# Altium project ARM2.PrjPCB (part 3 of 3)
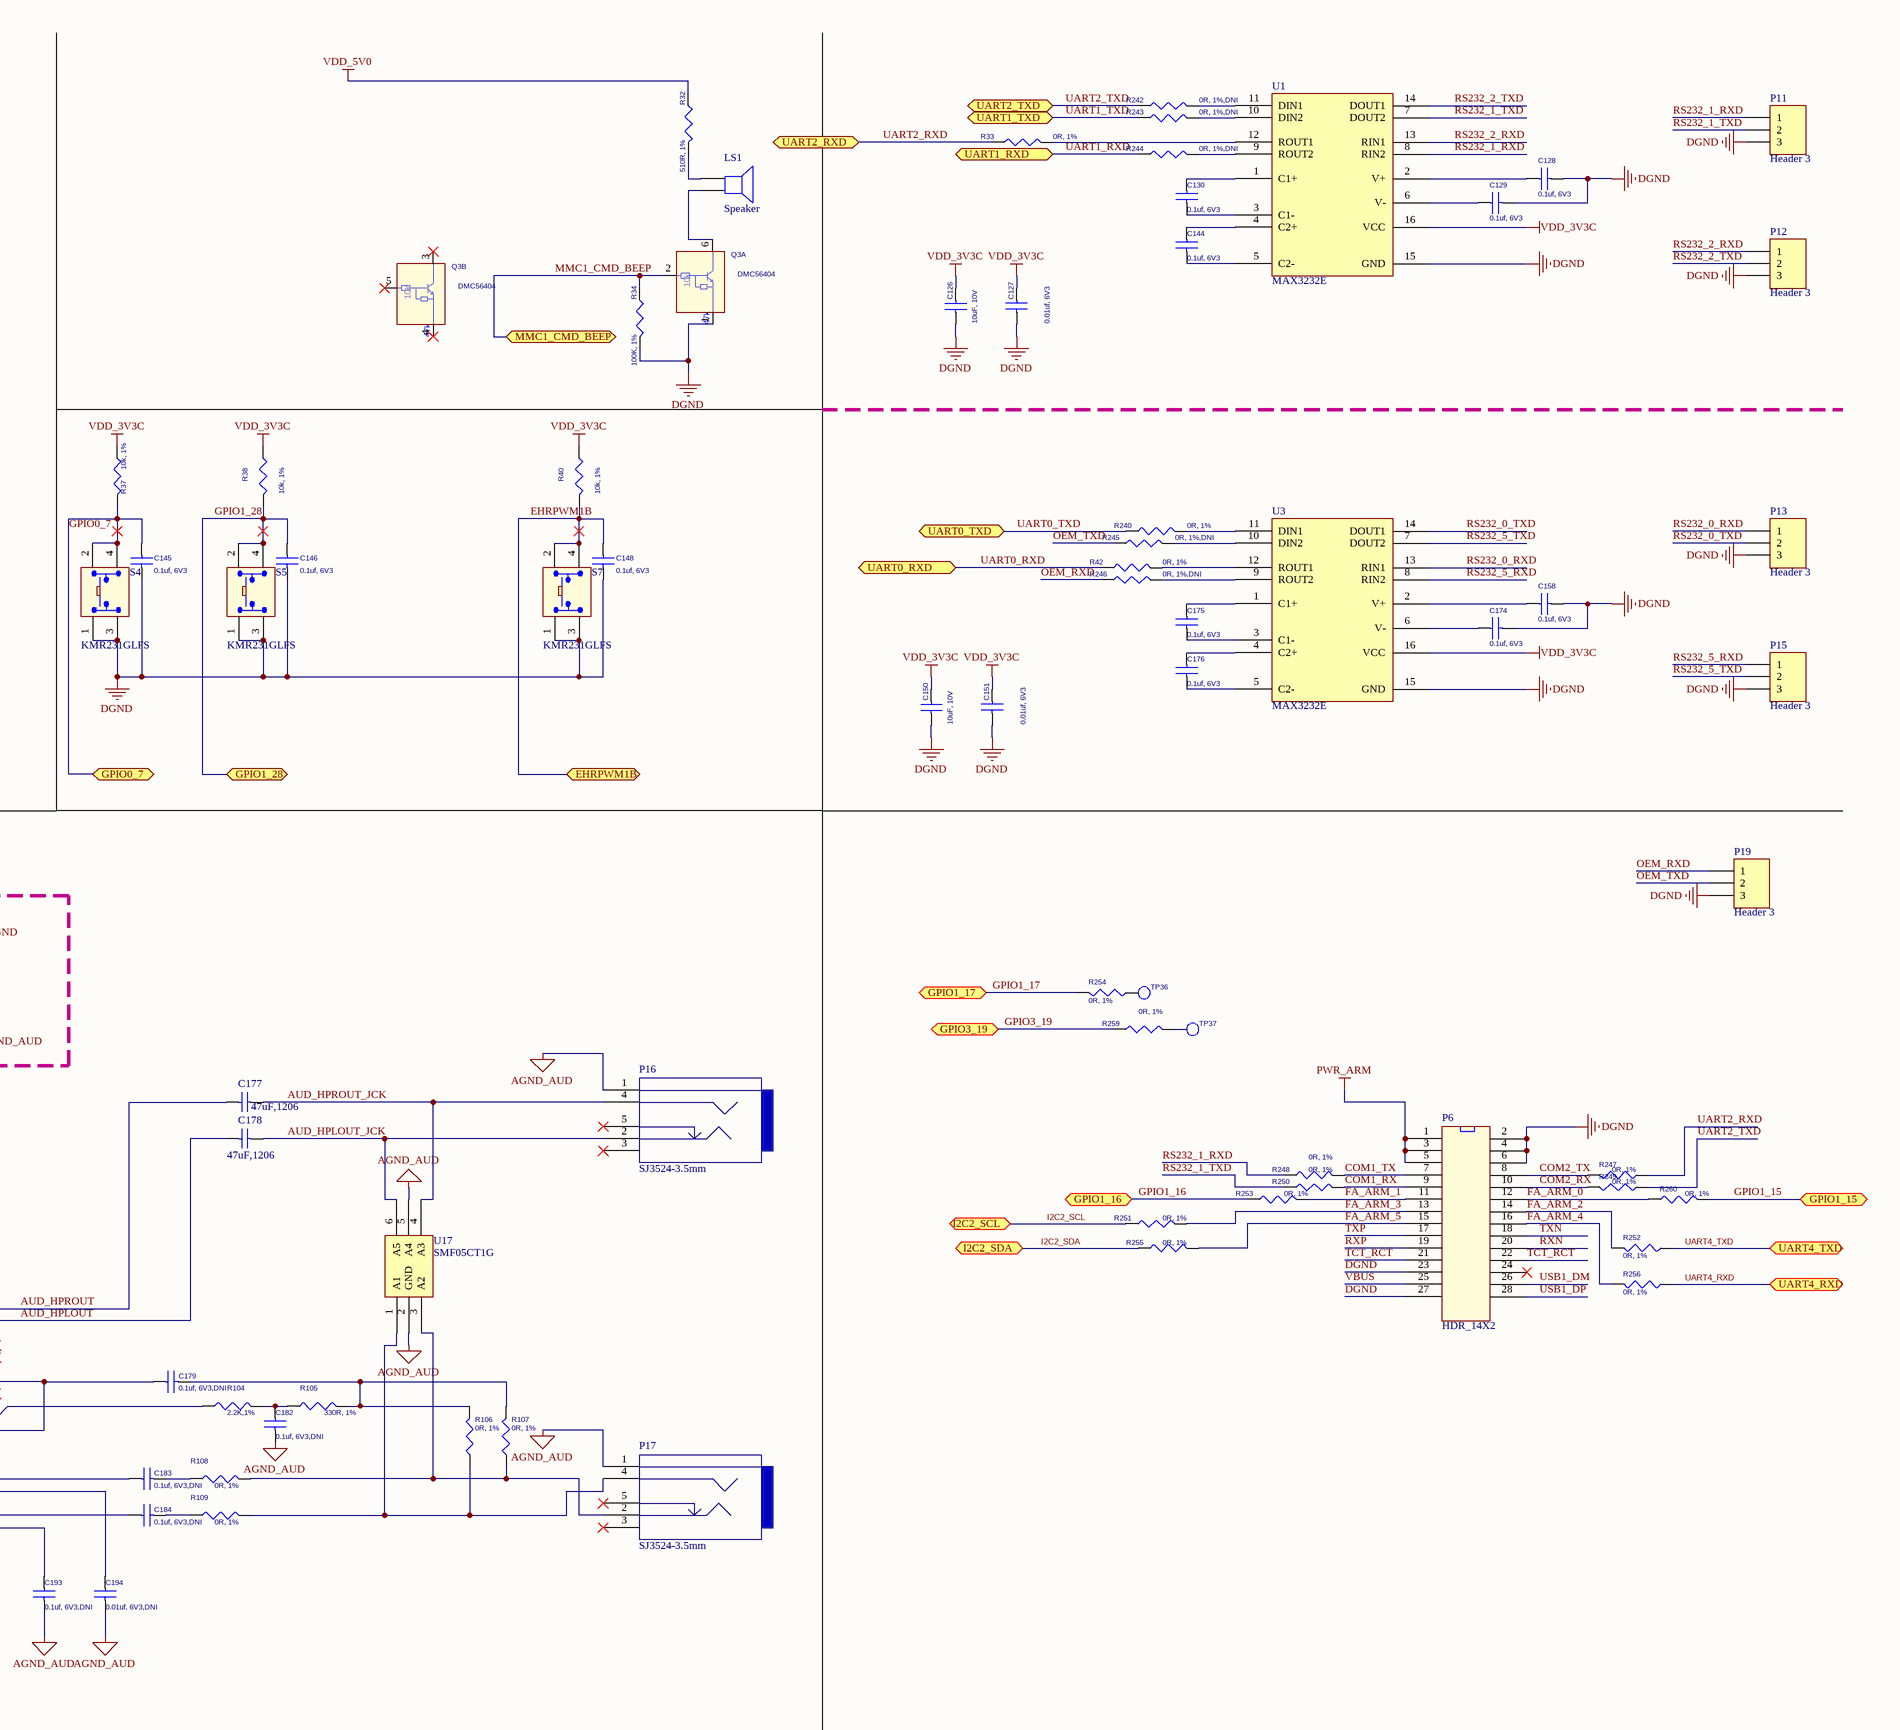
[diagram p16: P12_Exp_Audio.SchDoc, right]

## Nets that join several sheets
DDR_VREF: P03_Processor1_3 (C28.1 U5.J4), P07_DDR3_SDRAM (6 pins)
DGND: P02_PowerManagement (33 pins), P03_Processor1_3 (14 pins), P04_Processor2_3 (16 pins), P05_Processor3_3 (111 pins), P06_LED_BootConfig (26 pins), P07_DDR3_SDRAM (42 pins), P08_NandFlash (5 pins), P09_Ethernet (23 pins), P10_LCD (142 pins), P11_SDcard (7 pins), P12_Exp_Audio (46 pins)
GND_EARTH: P02_PowerManagement (6 pins), P04_Processor2_3 (P4.6 P4.7 P4.8 P4.9), P11_SDcard (6 pins)
GNDA_ADC: P04_Processor2_3 (C31.2 C32.2 C33.2 U5.A9), P05_Processor3_3 (C93.2 FB3.1 U5.E8), P11_SDcard (TP31.1)
SYS_5V: P02_PowerManagement (14 pins), P04_Processor2_3 (C34.1 U8.2 U8.3), P06_LED_BootConfig (R71.1 R72.1 R73.1 R74.1), P10_LCD (C200.1 U20.2), P11_SDcard (TP12.1)
USB_DC: P02_PowerManagement (C1.2 U2.12), P04_Processor2_3 (C36.1 P4.1 R159.1 U10.6)
VDD_1V8: P02_PowerManagement (C14.2 R9.2 U2.40), P05_Processor3_3 (9 pins)
VDD_3V3A: P02_PowerManagement (6 pins), P03_Processor1_3 (7 pins), P04_Processor2_3 (R52.1), P05_Processor3_3 (42 pins), P06_LED_BootConfig (16 pins), P10_LCD (U20.1), P11_SDcard (C152.1 R156.1 U7.4)
VDD_3V3B: P02_PowerManagement (C20.1 R11.1 U4.3), P03_Processor1_3 (C29.1 R23.1 R24.1), P04_Processor2_3 (C155.2 R163.1 U15.7 U15.8), P08_NandFlash (12 pins), P09_Ethernet (7 pins), P10_LCD (R158.1), P11_SDcard (11 pins)
VDD_5V: P02_PowerManagement (C2.2 R239.2 U2.10), P11_SDcard (TP11.1), P12_Exp_Audio (FB5.2)
VDD_5V0: P10_LCD (FB17.1 P9.1), P12_Exp_Audio (8 pins)
VDD_ADC: P04_Processor2_3 (R27.1), P05_Processor3_3 (C93.1 FB2.1 U5.D8), P11_SDcard (TP29.1)
VDD_CORE: P02_PowerManagement (C11.2 L3.2 U2.29), P05_Processor3_3 (37 pins)
VDD_MPU: P02_PowerManagement (C12.2 L2.2 U2.24), P05_Processor3_3 (11 pins)
VDDS: P02_PowerManagement (R8.2 R9.1), P05_Processor3_3 (13 pins)
VDDS_DDR: P02_PowerManagement (C9.2 R6.2), P05_Processor3_3 (16 pins), P07_DDR3_SDRAM (36 pins)
VIO: P02_PowerManagement (R7.2 U2.18), P03_Processor1_3 (U16.5)
VRTC: P02_PowerManagement (C16.1 R5.2), P04_Processor2_3 (R26.1), P05_Processor3_3 (C105.1 U5.D7)
12MHZ: P03_Processor1_3 (R21.2), P12_Exp_Audio (R103.1)
AIN4: P04_Processor2_3 (U5.C8), P11_SDcard (TP30.1)
AIN5: P04_Processor2_3 (U5.B8), P11_SDcard (TP33.1)
AIN6: P04_Processor2_3 (U5.A8), P11_SDcard (TP32.1)
CLKOUT2: P03_Processor1_3 (R19.2 R20.1), P11_SDcard (TP34.1)
DDR_A0: P03_Processor1_3 (U5.F3), P07_DDR3_SDRAM (U12.N3)
DDR_A1: P03_Processor1_3 (U5.H1), P07_DDR3_SDRAM (U12.P7)
DDR_A2: P03_Processor1_3 (U5.E4), P07_DDR3_SDRAM (U12.P3)
DDR_A3: P03_Processor1_3 (U5.C3), P07_DDR3_SDRAM (U12.N2)
DDR_A4: P03_Processor1_3 (U5.C2), P07_DDR3_SDRAM (U12.P8)
DDR_A5: P03_Processor1_3 (U5.B1), P07_DDR3_SDRAM (U12.P2)
DDR_A6: P03_Processor1_3 (U5.D5), P07_DDR3_SDRAM (U12.R8)
DDR_A7: P03_Processor1_3 (U5.E2), P07_DDR3_SDRAM (U12.R2)
DDR_A8: P03_Processor1_3 (U5.D4), P07_DDR3_SDRAM (U12.T8)
DDR_A9: P03_Processor1_3 (U5.C1), P07_DDR3_SDRAM (U12.R3)
DDR_A10: P03_Processor1_3 (U5.F4), P07_DDR3_SDRAM (U12.L7)
DDR_A11: P03_Processor1_3 (U5.F2), P07_DDR3_SDRAM (U12.R7)
DDR_A12: P03_Processor1_3 (U5.E3), P07_DDR3_SDRAM (U12.N7)
DDR_A13: P03_Processor1_3 (U5.H3), P07_DDR3_SDRAM (U12.T3)
DDR_A14: P03_Processor1_3 (U5.H4), P07_DDR3_SDRAM (U12.T7)
DDR_A15: P03_Processor1_3 (U5.D3), P07_DDR3_SDRAM (U12.M7)
DDR_BA0: P03_Processor1_3 (U5.C4), P07_DDR3_SDRAM (U12.M2)
DDR_BA1: P03_Processor1_3 (U5.E1), P07_DDR3_SDRAM (U12.N8)
DDR_BA2: P03_Processor1_3 (U5.B3), P07_DDR3_SDRAM (U12.M3)
DDR_CASn: P03_Processor1_3 (U5.F1), P07_DDR3_SDRAM (U12.K3)
DDR_CKE: P03_Processor1_3 (U5.G3), P07_DDR3_SDRAM (R96.2 U12.K9)
DDR_CLK: P03_Processor1_3 (U5.D2), P07_DDR3_SDRAM (U12.J7)
DDR_CLKn: P03_Processor1_3 (U5.D1), P07_DDR3_SDRAM (U12.K7)
DDR_CSn: P03_Processor1_3 (U5.H2), P07_DDR3_SDRAM (U12.L2)
DDR_D0: P03_Processor1_3 (U5.M3), P07_DDR3_SDRAM (U12.E3)
DDR_D1: P03_Processor1_3 (U5.M4), P07_DDR3_SDRAM (U12.F7)
DDR_D2: P03_Processor1_3 (U5.N1), P07_DDR3_SDRAM (U12.F2)
DDR_D3: P03_Processor1_3 (U5.N2), P07_DDR3_SDRAM (U12.F8)
DDR_D4: P03_Processor1_3 (U5.N3), P07_DDR3_SDRAM (U12.H3)
DDR_D5: P03_Processor1_3 (U5.N4), P07_DDR3_SDRAM (U12.H8)
DDR_D6: P03_Processor1_3 (U5.P3), P07_DDR3_SDRAM (U12.G2)
DDR_D7: P03_Processor1_3 (U5.P4), P07_DDR3_SDRAM (U12.H7)
DDR_D8: P03_Processor1_3 (U5.J1), P07_DDR3_SDRAM (U12.D7)
DDR_D9: P03_Processor1_3 (U5.K1), P07_DDR3_SDRAM (U12.C3)
DDR_D10: P03_Processor1_3 (U5.K2), P07_DDR3_SDRAM (U12.C8)
DDR_D11: P03_Processor1_3 (U5.K3), P07_DDR3_SDRAM (U12.C2)
DDR_D12: P03_Processor1_3 (U5.K4), P07_DDR3_SDRAM (U12.A7)
DDR_D13: P03_Processor1_3 (U5.L3), P07_DDR3_SDRAM (U12.A2)
DDR_D14: P03_Processor1_3 (U5.L4), P07_DDR3_SDRAM (U12.B8)
DDR_D15: P03_Processor1_3 (U5.M1), P07_DDR3_SDRAM (U12.A3)
DDR_DQM0: P03_Processor1_3 (U5.M2), P07_DDR3_SDRAM (U12.E7)
DDR_DQM1: P03_Processor1_3 (U5.J2), P07_DDR3_SDRAM (U12.D3)
DDR_DQS0: P03_Processor1_3 (U5.P1), P07_DDR3_SDRAM (U12.F3)
DDR_DQS1: P03_Processor1_3 (U5.L1), P07_DDR3_SDRAM (U12.C7)
DDR_DQSN0: P03_Processor1_3 (U5.P2), P07_DDR3_SDRAM (U12.G3)
DDR_DQSN1: P03_Processor1_3 (U5.L2), P07_DDR3_SDRAM (U12.B7)
DDR_ODT: P03_Processor1_3 (U5.G1), P07_DDR3_SDRAM (U12.K1)
DDR_RASn: P03_Processor1_3 (U5.G4), P07_DDR3_SDRAM (U12.J3)
DDR_RESETn: P03_Processor1_3 (U5.G2), P07_DDR3_SDRAM (R97.2 U12.T2)
DDR_WEn: P03_Processor1_3 (U5.B2), P07_DDR3_SDRAM (U12.L3)
EHRPWM1A: P03_Processor1_3 (U5.U14), P11_SDcard (TP18.1)
EHRPWM1B: P03_Processor1_3 (U5.T14), P11_SDcard (TP19.1), P12_Exp_Audio (C148.1 R40.2 S7.2 S7.4)
GPIO0_7: P04_Processor2_3 (R50.1 R51.1), P11_SDcard (TP35.1), P12_Exp_Audio (C145.1 R37.2 S4.2 S4.4)
GPIO1_15: P03_Processor1_3 (U5.U13), P12_Exp_Audio (R260.2)
GPIO1_16: P03_Processor1_3 (R160.2), P12_Exp_Audio (R253.1)
GPIO1_17: P03_Processor1_3 (U5.V14), P12_Exp_Audio (R254.2)
GPIO1_28: P03_Processor1_3 (U5.U18), P11_SDcard (TP16.1), P12_Exp_Audio (C146.1 R38.2 S5.2 S5.4)
GPIO3_19: P04_Processor2_3 (U5.C13), P12_Exp_Audio (R259.1)
GPIO3_20: P03_Processor1_3 (R20.2), P04_Processor2_3 (U5.D13)
GPIO3_21: P03_Processor1_3 (R167.2), P04_Processor2_3 (U5.A14), P11_SDcard (TP24.1), P12_Exp_Audio (R102.1)
HDMI_INT: P03_Processor1_3 (U5.U16), P10_LCD (R158.2)
I2C0_SCL: P02_PowerManagement (R3.2 U2.28), P04_Processor2_3 (U5.C16), P11_SDcard (U7.1)
I2C0_SDA: P02_PowerManagement (R4.2 U2.27), P04_Processor2_3 (U5.C17), P11_SDcard (U7.3)
I2C1_SCL: P04_Processor2_3 (U5.A16), P11_SDcard (TP20.1), P12_Exp_Audio (U11.1)
I2C1_SDA: P04_Processor2_3 (U5.B16), P11_SDcard (TP21.1), P12_Exp_Audio (U11.2)
I2C2_SCL: P04_Processor2_3 (U5.D17), P11_SDcard (TP22.1), P12_Exp_Audio (R251.1)
I2C2_SDA: P04_Processor2_3 (U5.D18), P11_SDcard (TP23.1), P12_Exp_Audio (R255.1)
LCD_DATA0: P04_Processor2_3 (U5.R1), P06_LED_BootConfig (R70.2 R95.1), P10_LCD (C173.1 RA5.2)
LCD_DATA1: P04_Processor2_3 (U5.R2), P06_LED_BootConfig (R69.2 R94.1), P10_LCD (C171.1 RA5.3)
LCD_DATA2: P04_Processor2_3 (U5.R3), P06_LED_BootConfig (R68.2 R75.1 R93.1), P10_LCD (C172.1 RA5.4)
LCD_DATA3: P04_Processor2_3 (U5.R4), P06_LED_BootConfig (R67.2 R92.1), P10_LCD (C170.1 RA6.1)
LCD_DATA4: P04_Processor2_3 (U5.T1), P06_LED_BootConfig (R66.2 R91.1), P10_LCD (C169.1 RA6.2)
LCD_DATA5: P04_Processor2_3 (U5.T2), P06_LED_BootConfig (R65.2 R90.1), P10_LCD (C163.1 RA3.3)
LCD_DATA6: P04_Processor2_3 (U5.T3), P06_LED_BootConfig (R64.2 R89.1), P10_LCD (C162.1 RA3.4)
LCD_DATA7: P04_Processor2_3 (U5.T4), P06_LED_BootConfig (R63.2 R88.1), P10_LCD (C161.1 RA4.1)
LCD_DATA8: P04_Processor2_3 (U5.U1), P06_LED_BootConfig (R62.2 R87.1), P10_LCD (C160.1 RA4.2)
LCD_DATA9: P04_Processor2_3 (U5.U2), P06_LED_BootConfig (R61.2 R86.1), P10_LCD (C157.1 RA4.3)
LCD_DATA10: P04_Processor2_3 (U5.U3), P06_LED_BootConfig (R60.2 R85.1), P10_LCD (C156.1 RA4.4)
LCD_DATA11: P04_Processor2_3 (U5.U4), P06_LED_BootConfig (R59.2 R84.1), P10_LCD (C168.1 RA2.2)
LCD_DATA12: P04_Processor2_3 (U5.V2), P06_LED_BootConfig (R58.2 R83.1), P10_LCD (C167.1 RA2.3)
LCD_DATA13: P04_Processor2_3 (U5.V3), P06_LED_BootConfig (R57.2 R82.1), P10_LCD (C166.1 RA2.4)
LCD_DATA14: P04_Processor2_3 (U5.V4), P06_LED_BootConfig (R56.2 R81.1), P10_LCD (C165.1 RA3.1)
LCD_DATA15: P04_Processor2_3 (U5.T5), P06_LED_BootConfig (R55.2 R80.1), P10_LCD (C164.1 RA3.2)
LCD_DE: P04_Processor2_3 (R48.2), P10_LCD (RA6.3)
LCD_HSYNC: P04_Processor2_3 (R47.2), P10_LCD (RA1.3)
LCD_PCLK: P04_Processor2_3 (R45.2), P10_LCD (R111.2)
LCD_VSYNC: P04_Processor2_3 (R46.2), P10_LCD (RA1.2)
LDO_PGOOD: P02_PowerManagement (U2.46), P03_Processor1_3 (U5.B5)
MDIO_CLK: P04_Processor2_3 (U5.M18), P09_Ethernet (U14.17)
MDIO_DATA: P04_Processor2_3 (U5.M17), P09_Ethernet (R119.2 U14.16)
MII1_COL: P04_Processor2_3 (U5.H16), P09_Ethernet (R138.1)
MII1_CRS_DV: P04_Processor2_3 (U5.H17), P09_Ethernet (R139.1)
MII1_REFCLK: P04_Processor2_3 (R28.2), P09_Ethernet (R124.1 R140.1)
MII1_RXCLK: P04_Processor2_3 (U5.L18), P09_Ethernet (R131.1)
MII1_RXD0: P04_Processor2_3 (U5.M16), P09_Ethernet (R128.1)
MII1_RXD1: P04_Processor2_3 (U5.L15), P09_Ethernet (R127.1)
MII1_RXD2: P04_Processor2_3 (U5.L16), P09_Ethernet (R126.1)
MII1_RXD3: P04_Processor2_3 (U5.L17), P09_Ethernet (R125.1)
MII1_RXDV: P04_Processor2_3 (U5.J17), P09_Ethernet (R129.1)
MII1_RXERR: P04_Processor2_3 (U5.J15), P09_Ethernet (R133.1)
MII1_TXCLK: P04_Processor2_3 (U5.K18), P09_Ethernet (R134.1)
MII1_TXD0: P04_Processor2_3 (U5.K17), P09_Ethernet (U14.22)
MII1_TXD1: P04_Processor2_3 (U5.K16), P09_Ethernet (U14.23)
MII1_TXD2: P04_Processor2_3 (U5.K15), P09_Ethernet (U14.24)
MII1_TXD3: P04_Processor2_3 (U5.J18), P09_Ethernet (U14.25)
MII1_TXEN: P04_Processor2_3 (U5.J16), P09_Ethernet (U14.21)
MMC0_CD: P04_Processor2_3 (U5.C15), P11_SDcard (P10.10 R157.1)
MMC0_CLKO: P03_Processor1_3 (U5.G17), P11_SDcard (P10.5 R152.2)
MMC0_CMD: P03_Processor1_3 (U5.G18), P11_SDcard (P10.3 R151.2)
MMC0_DAT0: P03_Processor1_3 (U5.G16), P11_SDcard (P10.7 R153.2)
MMC0_DAT1: P03_Processor1_3 (U5.G15), P11_SDcard (P10.8 R154.2)
MMC0_DAT2: P03_Processor1_3 (U5.F18), P11_SDcard (P10.1 R150.2)
MMC0_DAT3: P03_Processor1_3 (U5.F17), P11_SDcard (P10.2 R155.2)
MMC1_CMD_BEEP: P03_Processor1_3 (U5.V9), P12_Exp_Audio (Q3.2 R34.1)
NAND_ALE: P03_Processor1_3 (U5.R7), P08_NandFlash (U13.17)
NAND_CLE: P03_Processor1_3 (U5.T6), P08_NandFlash (U13.16)
NAND_CSn0: P03_Processor1_3 (U5.V6), P08_NandFlash (R29.1 U13.9)
NAND_CSn3: P03_Processor1_3 (U5.T13), P08_NandFlash (R16.1 U13.10)
NAND_D0: P03_Processor1_3 (U5.U7), P08_NandFlash (U13.29)
NAND_D1: P03_Processor1_3 (U5.V7), P08_NandFlash (U13.30)
NAND_D2: P03_Processor1_3 (U5.R8), P08_NandFlash (U13.31)
NAND_D3: P03_Processor1_3 (U5.T8), P08_NandFlash (U13.32)
NAND_D4: P03_Processor1_3 (U5.U8), P08_NandFlash (U13.41)
NAND_D5: P03_Processor1_3 (U5.V8), P08_NandFlash (U13.42)
NAND_D6: P03_Processor1_3 (U5.R9), P08_NandFlash (U13.43)
NAND_D7: P03_Processor1_3 (U5.T9), P08_NandFlash (U13.44)
NAND_OEn: P03_Processor1_3 (U5.T7), P08_NandFlash (R31.1 U13.8)
NAND_WAIT0: P03_Processor1_3 (U5.T17), P08_NandFlash (R13.1 U13.7), P11_SDcard (TP15.1)
NAND_WAIT1: P03_Processor1_3 (U5.V12), P08_NandFlash (R15.1 U13.6)
NAND_WEn: P03_Processor1_3 (U5.U6), P08_NandFlash (R30.1 U13.18)
NAND_WPn: P03_Processor1_3 (U5.U17), P08_NandFlash (R2.1 U13.19), P11_SDcard (TP17.1)
PMIC_INT: P02_PowerManagement (R1.2 U2.45), P03_Processor1_3 (U5.B18)
PMIC_PGOOD: P02_PowerManagement (U2.26), P03_Processor1_3 (U5.B15 U16.2)
PMIC_POWR_EN: P02_PowerManagement (U2.9), P04_Processor2_3 (U5.C6)
PWR_BUT: P02_PowerManagement (S3.2 S3.4 U2.25), P11_SDcard (TP13.1)
RXN: P09_Ethernet (C138.1 R121.1 U14.30), P12_Exp_Audio (P6.20)
RXP: P09_Ethernet (C137.1 R120.1 U14.31), P12_Exp_Audio (P6.19)
SPI1_CS0: P04_Processor2_3 (U5.C12), P11_SDcard (TP25.1), P12_Exp_Audio (U11.41)
SPI1_D0: P04_Processor2_3 (U5.B13), P11_SDcard (TP26.1), P12_Exp_Audio (U11.39)
SPI1_D1: P04_Processor2_3 (U5.D12), P11_SDcard (TP27.1), P12_Exp_Audio (U11.40)
SPI1_SCLK: P04_Processor2_3 (U5.A13), P11_SDcard (TP28.1), P12_Exp_Audio (U11.38)
SYS_RESETn: P03_Processor1_3 (7 pins), P09_Ethernet (U14.19), P11_SDcard (TP14.1), P12_Exp_Audio (R44.1)
TCT_RCT: P09_Ethernet (C141.1 R137.1), P12_Exp_Audio (P6.21 P6.22)
TXN: P09_Ethernet (C140.1 R123.1 U14.28), P12_Exp_Audio (P6.18)
TXP: P09_Ethernet (C139.1 R122.1 U14.29), P12_Exp_Audio (P6.17)
UART0_RXD: P04_Processor2_3 (U5.E15 U15.6), P12_Exp_Audio (R42.1)
UART0_TXD: P04_Processor2_3 (U5.E16 U15.5), P12_Exp_Audio (R240.1)
UART1_RXD: P04_Processor2_3 (U5.D16), P12_Exp_Audio (R244.1)
UART1_TXD: P04_Processor2_3 (U5.D15), P12_Exp_Audio (R243.1)
UART2_RXD: P04_Processor2_3 (U5.A17), P12_Exp_Audio (R33.1 R247.1)
UART2_TXD: P04_Processor2_3 (U5.B17), P12_Exp_Audio (R242.1 R249.1)
UART4_RXD: P04_Processor2_3 (U5.E18), P12_Exp_Audio (R256.1)
UART4_TXD: P04_Processor2_3 (U5.E17), P12_Exp_Audio (R252.1)
USB1_DM: P04_Processor2_3 (U5.R18 U9.2), P12_Exp_Audio (P6.26)
USB1_DP: P04_Processor2_3 (U5.R17 U9.1), P12_Exp_Audio (P6.28)
USB1_OCn: P03_Processor1_3 (U5.T16), P04_Processor2_3 (R52.2 U8.5)
USR0: P03_Processor1_3 (U5.V15), P06_LED_BootConfig (Q1.2 R76.1)
USR1: P03_Processor1_3 (U5.U15), P06_LED_BootConfig (Q1.5 R77.1)
USR2: P03_Processor1_3 (U5.T15), P06_LED_BootConfig (Q2.2 R78.1)
USR3: P03_Processor1_3 (U5.V16), P06_LED_BootConfig (Q2.5 R79.1)
VBUS: P04_Processor2_3 (FB7.2), P12_Exp_Audio (P6.25)
WAKEUP: P02_PowerManagement (U2.13), P04_Processor2_3 (R26.2 U5.C5)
